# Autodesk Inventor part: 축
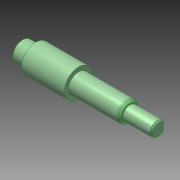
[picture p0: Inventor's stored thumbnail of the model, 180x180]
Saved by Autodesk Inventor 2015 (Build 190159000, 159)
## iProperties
Created: 2023-11
Part Number: 축
Material: 강철, 연강
Document SubType Name: Modeling
Designer: mdu-01
Density: 1 g/cm^3
Appearance: 강철(1)
Author: mdu-01
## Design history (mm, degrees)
sketch "스케치1"
  geometry: L1 (0, 0)-(96, 0); L2 (0, 0)-(0, 6); L3 (1, 7)-(10, 7); L4 (10, 7)-(10, 10); L5 (10, 10)-(40, 10); L6 (40, 10)-(40, 7); L7 (40, 7)-(73.732, 7); L8 (76, 5.711)-(76, 5); L9 (76, 5)-(95, 5); L10 (96, 4)-(96, 0); L11 (0, 6)-(1, 7); L12 (95, 5)-(96, 4); L13 (74.732, 6.732)-(75.75, 6.144); L14 (14, 10)-(14, 7); L15 (14, 7)-(36, 7); L16 (36, 7)-(36, 10); L17 (96, 3.2)-(86, 3.2); L18 (86, 3.2)-(86, 5); A1 r 0.5 centre (75.5, 5.711) between (76, 5.711) and (75.75, 6.144); A2 r 2 centre (73.732, 5) between (74.732, 6.732) and (73.732, 7); 5 further points
  constraints: 36 end point, 10 point on line, 7 parallel, 5 perpendicular, 4 point on circle, 4 tangent, 2 centre point, 2 collinear, 2 horizontal, 2 midpoint, 1 vertical alignment
  dimensions: "d0" = 96 distance of L1.start L1.end; "d1" = 14 diameter of L3 L1; "d2" = 10 distance between parallel lines of L4 L2; "d3" = 30 distance between parallel lines of L6 L4; "d4" = 20 diameter of L5 L1; "d5" = 36 distance between parallel lines of L8 L6; "d6" = 10 diameter of L9 L1; "d7" = 1 distance of L2.end point (0, 7); "d8" = 1 distance of L3.start point (0, 7) (= d7); "d9" = 1 distance of L9.end point (96, 5) (= d7); "d10" = 1 distance of L10.start point (96, 5) (= d9); "d11" = 12 diameter of point (76, 6) L1; "d12" = 30 deg angle of L13 L7; "d13" = 0.5 radius of A1; "d14" = 2 radius of A2; "d15" = 3 distance between parallel lines of L15 L5; "d16" = 22 distance between parallel lines of L16 L14; "d17" = 1.8 distance between parallel lines of L17 L9; "d18" = 10 distance between parallel lines of L18 L10
revolve "회전1" stored, may be unused: angle "d19" = 90 deg
extrude "돌출1" cut sketch "스케치1" stored distance "d20" = 5; taper "d21" = 0 deg
extrude "돌출2" cut sketch "스케치1" stored distance "d22" = 3; taper "d23" = 0 deg
fillet "모깎기1"
fillet "모깎기2"
fillet "모깎기3"
node "솔리드1"
